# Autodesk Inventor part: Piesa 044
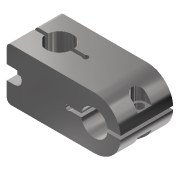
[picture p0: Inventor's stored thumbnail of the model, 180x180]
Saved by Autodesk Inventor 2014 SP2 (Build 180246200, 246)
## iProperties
Created: 2009-01
Part Number: Piesa 044
Document SubType Name: Modeling
Designer: Costel
Material: Steel
Density: 7.85 g/cm^3
Appearance: Steel - Polished
Author: Costel
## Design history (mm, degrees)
sketch "Sketch2"
  geometry: L1 (0, -37.243)-(0, 49.657) reference; L2 (114.139, 0)-(-69.311, 0) reference; L3 (95, 30)-(0, 30); L4 (95, -30)-(0, -30); L5 (100, 25)-(100, -25); A1 r 30 centre (0, 0) between (0, 30) and (0, -30); A2 r 5 centre (95, 25) between (100, 25) and (95, 30); A3 r 5 centre (95, -25) between (95, -30) and (100, -25)
  constraints: 6 end point, 6 point on circle, 4 tangent, 3 centre point, 2 parallel, 2 point on line, 1 equal radius, 1 perpendicular, 1 other
  dimensions: "d0" = 30 radius of A1; "d1" = 100 distance from line of L5 A1.centre; "d2" = 5 radius of A2
extrude "Extrusion1" new body sketch "Sketch2" stored distance "d3" = 60; taper "d4" = 0 deg
sketch "Sketch3"
  geometry: L1 (0, 0)-(0, -60) reference; L2 (95, -60)-(95, 0) reference; L3 (95, -66)-(95, 18) reference; L4 (0, -30)-(95, -30); L5 (-5, 0)-(-5, -60) reference; L6 (-5, -28)-(10.134, -28); L7 (39.866, -28)-(52.764, -28); L8 (-5, -32)-(10.134, -32); L9 (39.866, -32)-(52.764, -32); L10 (-5, -32)-(-5, -28); A1 r 3 centre (55, -30) between (52.764, -32) and (52.764, -28); A2 r 15 centre (25, -30) between (39.866, -28) and (10.134, -28); A3 r 15 centre (25, -30) between (10.134, -32) and (39.866, -32)
  constraints: 12 end point, 6 parallel, 6 point on circle, 5 point on line, 3 centre point, 2 collinear, 2 perpendicular, 1 midpoint, 1 other
  dimensions: "d5" = 70 distance from line of L2 A2.centre; "d8" = 6 diameter of A1; "d9" = 4 distance between parallel lines of L8 L6; "d15" = 15 radius of A2; "d16" = 15 radius of A3; "d17" = 30 distance of A1.centre A2.centre
extrude "Extrusion2" cut sketch "Sketch3" stored distance "d10" = 60; taper "d11" = 0 deg
sketch "Sketch4"
  geometry: L1 (0, -30)-(-95, -30) reference; L2 (-114.682, 0)-(76.372, 0) reference; L3 (29.933, 2)-(14.866, 2); L4 (-14.866, 2)-(-27.764, 2); L5 (29.933, -2)-(14.866, -2); L6 (-14.866, -2)-(-27.764, -2); A1 r 30 centre (0, 0) between (0, -30) and (0, 30) reference; A2 r 3 centre (-30, 0) between (-27.764, 2) and (-27.764, -2); A3 r 15 centre (0, 0) between (14.866, 2) and (-14.866, 2); A4 r 15 centre (0, 0) between (-14.866, -2) and (14.866, -2); A5 r 30 centre (0, 0) between (29.933, -2) and (29.933, 2)
  constraints: 11 point on circle, 9 end point, 6 parallel, 4 centre point, 2 coincident, 2 collinear, 1 point on line, 1 other
  dimensions: "d18" = 15 radius of A3; "d19" = 15 radius of A4; "d20" = 4 distance between parallel lines of L5 L3; "d21" = 3 radius of A2; "d22" = 30 distance of A1.centre A2.centre
extrude "Extrusion3" cut sketch "Sketch4" stored distance "d23" = 60; taper "d24" = 0 deg
sketch "Sketch5"
  geometry: L1 (-100, -25)-(-100, 25) reference; L2 (-114.685, 0)-(76.409, 0) reference; L3 (-91, 8)-(-100, 8); L4 (-91, -8)-(-100, -8); L5 (-100, 8)-(-100, -8); A1 r 15 centre (0, 0) between (-14.866, -2) and (14.866, -2) reference; A2 r 8 centre (-91, 0) between (-91, -8) and (-91, 8)
  constraints: 6 end point, 3 perpendicular, 3 point on line, 2 point on circle, 2 tangent, 1 centre point
  dimensions: "d25" = 8 radius of A2; "d26" = 91 distance of A1.centre A2.centre
extrude "Extrusion4" cut sketch "Sketch5" distance "d27" = 12; taper "d28" = 0 deg
hole "Hole1" diameter "d31" = 10; stored, may be unused: countersink angle "d35" = 90 deg, drill point angle "d37" = 118 deg; dims "d29" = 10, "d30" = 10, "d32" = 6, "d33" = 4, "d34" = 2, "d36" = 8
workplane "Work Plane1"
sketch "Sketch6"
  geometry: L1 (0, -36)-(0, 48) reference; L2 (29.933, -30)-(29.933, 30) reference; L3 (-112.993, 0)-(68.913, 0) reference; L4 (21, 8)-(29.982, 8); L5 (21, -8)-(29.933, -8); L6 (29.982, 8)-(29.933, -8); A1 r 8 centre (21, 0) between (21, 8) and (21, -8)
  constraints: 6 end point, 2 parallel, 2 point on circle, 2 point on line, 2 tangent, 1 centre point
  dimensions: "d50" = 8 radius of A1; "d51" = 21 distance from line of L1 A1.centre
extrude "Extrusion5" cut sketch "Sketch6" stored distance "d39" = 12; taper "d40" = 0 deg
hole "Hole2" diameter "d43" = 10; stored, may be unused: countersink angle "d47" = 90 deg, drill point angle "d49" = 118 deg; dims "d41" = 10, "d42" = 10, "d44" = 6, "d45" = 4, "d46" = 2, "d48" = 8
workplane "Work Plane2"
mirror "Mirror1"
body "Solid1"
other parameters: "d7" = 4, "d38" = 12, "d52" = 0
